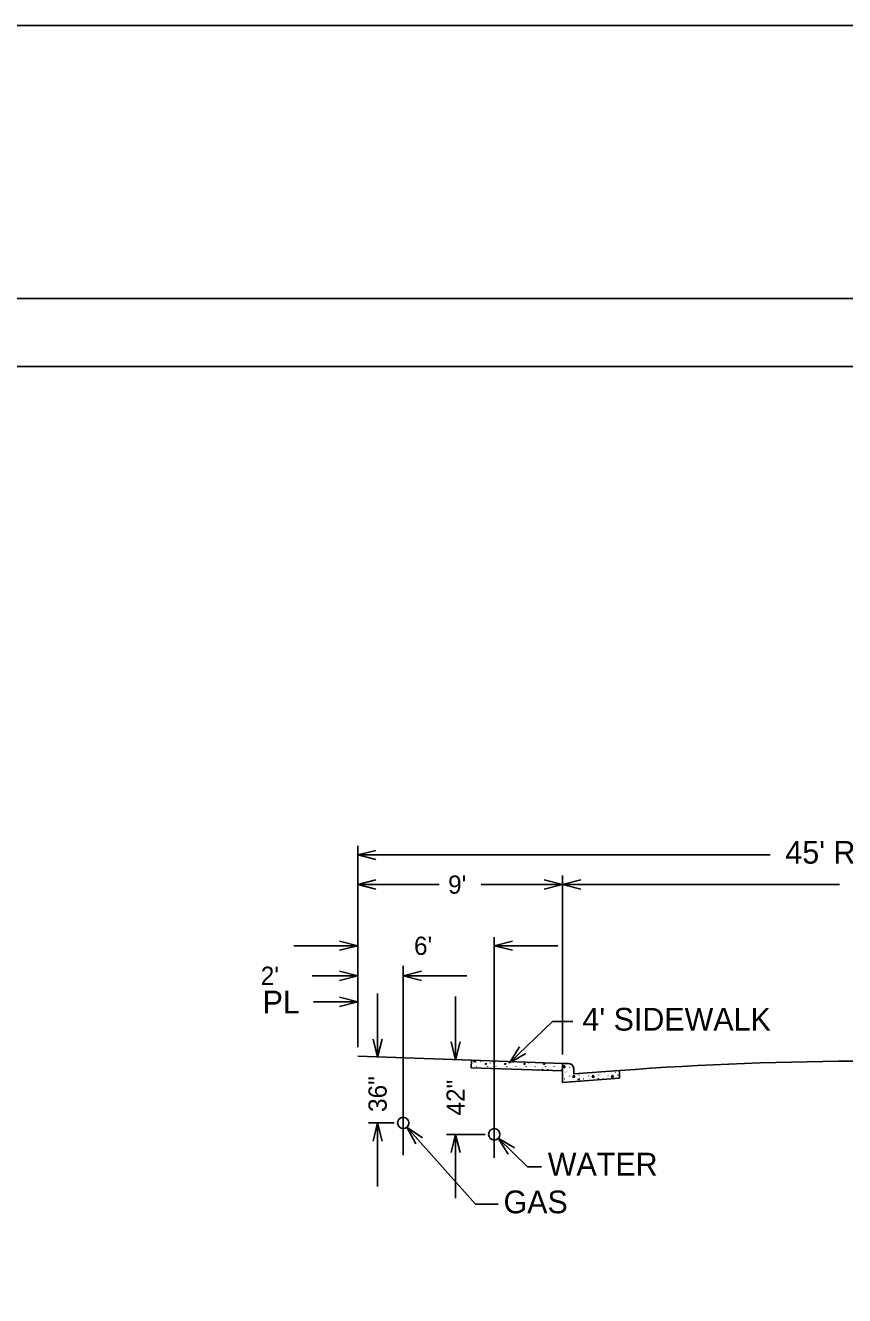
# Model space of a CAD drawing. Extents: x 524397 to 525117, y 3701341 to 3701821.
# Drawn here: x 524706.5 to 524778.5, y 3701709.3 to 3701821 of the extents above; entities that cross this region are included whole.
import ezdxf

# ---------------------------------------------------------------- set-up
doc = ezdxf.new("R2010")
doc.units = 0
for name, color, linetype in [('Level 1', 7, 'Continuous'), ('Level 11', 7, 'Continuous'), ('Level 9', 7, 'Continuous'), ('Pam batch print border', 7, 'Continuous')]:
    doc.layers.add(name, color=color, linetype=linetype)

msp = doc.modelspace()

# ---------------------------------------------------------------- linework, layer by layer
at = {"layer": 'Level 1'}
msp.add_line((524442.4, 3701790.98), (525097.4, 3701790.98), dxfattribs=at)
at = {"layer": 'Level 11'}
for p, q in [((524735.75, 3701731.14), (524735.75, 3701748.85)), ((524735.75, 3701748.05), (524737.35, 3701748.45)), ((524771.99, 3701748.05), (524735.75, 3701748.05)), ((524737.35, 3701747.65), (524735.75, 3701748.05)), ((524735.75, 3701731.28), (524735.75, 3701746.25)), ((524735.75, 3701745.45), (524737.35, 3701745.85)), ((524752.14, 3701745.85), (524753.75, 3701745.45)), ((524753.75, 3701730.51), (524753.75, 3701746.25)), ((524753.75, 3701745.45), (524755.35, 3701745.85)), ((524742.89, 3701745.45), (524735.75, 3701745.45)), ((524737.35, 3701745.05), (524735.75, 3701745.45)), ((524746.61, 3701745.45), (524753.75, 3701745.45)), ((524753.75, 3701745.45), (524752.14, 3701745.05)), ((524778.09, 3701745.45), (524753.75, 3701745.45)), ((524755.35, 3701745.05), (524753.75, 3701745.45)), ((524734.14, 3701740.46), (524735.75, 3701740.06)), ((524747.75, 3701721.41), (524747.75, 3701740.83)), ((524747.75, 3701740.06), (524749.35, 3701740.46)), ((524730.14, 3701740.06), (524735.75, 3701740.06)), ((524735.75, 3701740.06), (524734.14, 3701739.66)), ((524753.35, 3701740.06), (524747.75, 3701740.06)), ((524749.35, 3701739.66), (524747.75, 3701740.06)), ((524735.75, 3701731.51), (524735.75, 3701738.51)), ((524739.75, 3701721.64), (524739.75, 3701738.29)), ((524731.74, 3701737.42), (524735.75, 3701737.42)), ((524734.14, 3701737.82), (524735.75, 3701737.42)), ((524735.75, 3701737.42), (524734.14, 3701737.02)), ((524739.75, 3701737.42), (524741.35, 3701737.82)), ((524745.35, 3701737.42), (524739.75, 3701737.42)), ((524741.35, 3701737.02), (524739.75, 3701737.42)), ((524737.49, 3701735.87), (524737.49, 3701730.26)), ((524735.75, 3701735.13), (524731.87, 3701735.13)), ((524734.14, 3701735.53), (524735.75, 3701735.13)), ((524735.75, 3701735.13), (524734.14, 3701734.73)), ((524735.75, 3701731.51), (524735.75, 3701735.58)), ((524744.35, 3701735.6), (524744.35, 3701730)), ((524749.08, 3701729.78), (524752.86, 3701733.39)), ((524752.86, 3701733.39), (524754.66, 3701733.39)), ((524737.49, 3701730.26), (524737.09, 3701731.86)), ((524737.89, 3701731.86), (524737.49, 3701730.26)), ((524744.35, 3701730), (524743.95, 3701731.6)), ((524744.75, 3701731.6), (524744.35, 3701730)), ((524745.75, 3701729.99), (524735.75, 3701730.34)), ((524749.96, 3701731.18), (524749.08, 3701729.78)), ((524749.08, 3701729.78), (524750.51, 3701730.6)), ((524745.75, 3701729.99), (524745.73, 3701729.33)), ((524745.73, 3701729.33), (524753.75, 3701729.05)), ((524753.75, 3701729.71), (524745.75, 3701729.99)), ((524746.21, 3701729.45), (524746.2, 3701729.48)), ((524746.54, 3701729.86), (524746.52, 3701729.89)), ((524747.14, 3701729.44), (524747.12, 3701729.42)), ((524747.15, 3701729.45), (524747.14, 3701729.43)), ((524747.39, 3701729.77), (524747.39, 3701729.74)), ((524747.92, 3701729.45), (524747.9, 3701729.48)), ((524748.24, 3701729.86), (524748.23, 3701729.89)), ((524748.84, 3701729.44), (524748.83, 3701729.42)), ((524748.85, 3701729.45), (524748.84, 3701729.43)), ((524749.1, 3701729.77), (524749.09, 3701729.74)), ((524749.62, 3701729.45), (524749.6, 3701729.48)), ((524750.54, 3701729.44), (524750.53, 3701729.42)), ((524750.56, 3701729.45), (524750.54, 3701729.43)), ((524750.76, 3701729.18), (524750.75, 3701729.22)), ((524750.8, 3701729.77), (524750.79, 3701729.74)), ((524751.32, 3701729.45), (524751.3, 3701729.48)), ((524751.6, 3701729.13), (524751.59, 3701729.13)), ((524752.24, 3701729.44), (524752.23, 3701729.42)), ((524752.26, 3701729.45), (524752.24, 3701729.43)), ((524752.47, 3701729.18), (524752.45, 3701729.22)), ((524752.5, 3701729.76), (524752.5, 3701729.74)), ((524753.02, 3701729.45), (524753.01, 3701729.48)), ((524753.31, 3701729.1), (524753.29, 3701729.13)), ((524753.75, 3701728.05), (524753.75, 3701729.71)), ((524753.75, 3701729.71), (524754.26, 3701729.71)), ((524753.75, 3701729.05), (524753.75, 3701729.71)), ((524754.06, 3701728.94), (524754.05, 3701728.97)), ((524754.26, 3701729.71), (524754.25, 3701729.71)), ((524754.39, 3701729.35), (524754.37, 3701729.39)), ((524754.75, 3701729.25), (524754.75, 3701728.79)), ((524754.75, 3701728.79), (524758.75, 3701729.09)), ((524757.47, 3701728.94), (524757.45, 3701728.97)), ((524758.75, 3701729.09), (524758.75, 3701728.43)), ((524758.75, 3701728.43), (524753.75, 3701728.05)), ((524753.91, 3701728.37), (524753.89, 3701728.35)), ((524754.35, 3701728.6), (524754.34, 3701728.63)), ((524755.21, 3701728.68), (524755.2, 3701728.71)), ((524755.61, 3701728.37), (524755.6, 3701728.35)), ((524756.05, 3701728.6), (524756.04, 3701728.63)), ((524756.69, 3701728.93), (524756.68, 3701728.91)), ((524756.7, 3701728.94), (524756.69, 3701728.92)), ((524756.91, 3701728.68), (524756.9, 3701728.71)), ((524757.31, 3701728.37), (524757.3, 3701728.35)), ((524757.76, 3701728.6), (524757.74, 3701728.63)), ((524758.39, 3701728.93), (524758.38, 3701728.91)), ((524758.41, 3701728.94), (524758.39, 3701728.92)), ((524758.62, 3701728.68), (524758.6, 3701728.71)), ((524738.95, 3701724.48), (524736.69, 3701724.48)), ((524737.09, 3701722.88), (524737.49, 3701724.48)), ((524737.49, 3701718.88), (524737.49, 3701724.48)), ((524737.49, 3701724.48), (524737.89, 3701722.88)), ((524740.84, 3701722.64), (524740.07, 3701724.1)), ((524740.07, 3701724.1), (524741.44, 3701723.17)), ((524740.07, 3701724.1), (524746.1, 3701717.35)), ((524746.95, 3701723.48), (524743.55, 3701723.48)), ((524743.95, 3701721.88), (524744.35, 3701723.48)), ((524744.35, 3701717.88), (524744.35, 3701723.48)), ((524744.35, 3701723.48), (524744.75, 3701721.88)), ((524748.97, 3701721.73), (524748.1, 3701723.13)), ((524748.1, 3701723.13), (524749.53, 3701722.3)), ((524748.1, 3701723.13), (524750.67, 3701720.63)), ((524750.67, 3701720.63), (524751.91, 3701720.63)), ((524746.1, 3701717.35), (524748.09, 3701717.35))]:
    msp.add_line(p, q, dxfattribs=at)
for points in [[(524746.04, 3701729.98), (524745.95, 3701729.89), (524746.1, 3701729.82)], [(524746.11, 3701729.82), (524746.08, 3701729.98)], [(524747.07, 3701729.63), (524747.03, 3701729.72), (524746.96, 3701729.67), (524747.07, 3701729.63)], [(524747.68, 3701729.92), (524747.65, 3701729.89), (524747.8, 3701729.82)], [(524747.81, 3701729.82), (524747.79, 3701729.92)], [(524748.77, 3701729.63), (524748.73, 3701729.72), (524748.66, 3701729.67), (524748.77, 3701729.63)], [(524749.42, 3701729.86), (524749.51, 3701729.82)], [(524749.51, 3701729.82), (524749.5, 3701729.86)], [(524750.3, 3701729.17), (524750.29, 3701729.19), (524750.28, 3701729.17)], [(524750.47, 3701729.63), (524750.43, 3701729.72), (524750.36, 3701729.67), (524750.47, 3701729.63)], [(524752.03, 3701729.11), (524751.99, 3701729.19), (524751.96, 3701729.12)], [(524752.18, 3701729.63), (524752.13, 3701729.72), (524752.06, 3701729.67), (524752.18, 3701729.63)], [(524753.75, 3701729.09), (524753.69, 3701729.19), (524753.63, 3701729.06)], [(524753.96, 3701729.32), (524753.93, 3701729.52), (524753.8, 3701729.39), (524753.95, 3701729.32)], [(524754.42, 3701728.1), (524754.42, 3701728.11), (524754.4, 3701728.1)], [(524754.83, 3701728.5), (524754.74, 3701728.68), (524754.66, 3701728.52), (524754.83, 3701728.5)], [(524755.24, 3701728.28), (524755.19, 3701728.37), (524755.12, 3701728.31), (524755.24, 3701728.28)], [(524756.53, 3701728.5), (524756.44, 3701728.68), (524756.36, 3701728.52), (524756.53, 3701728.5)], [(524756.93, 3701728.29), (524756.9, 3701728.37), (524756.83, 3701728.31), (524756.9, 3701728.29)], [(524758.24, 3701728.5), (524758.14, 3701728.68), (524758.06, 3701728.52), (524758.23, 3701728.5)]]:
    msp.add_lwpolyline(points, dxfattribs=at)
for centre in [(524739.75, 3701724.48), (524747.75, 3701723.48)]:
    msp.add_circle(centre, 0.5, dxfattribs=at)
for centre, radius, start, end in [((524754.25, 3701729.22), 0.494, 3.7079, 90.7668), ((524780.75, 3701437.7), 292.22, 85.6824, 94.3176)]:
    msp.add_arc(centre, radius, start, end, dxfattribs=at)
at = {"layer": 'Level 9'}
msp.add_lwpolyline([(524396.79, 3701820.98), (525116.79, 3701820.98), (525116.79, 3701340.98), (524396.79, 3701340.98)], close=True, dxfattribs=at)
at = {"layer": 'Pam batch print border'}
msp.add_lwpolyline([(524433.4, 3701796.98), (525105.4, 3701796.98), (525105.4, 3701364.98), (524433.4, 3701364.98)], close=True, dxfattribs=at)
msp.add_lwpolyline([(524433.4, 3701796.98), (525105.4, 3701796.98), (525105.4, 3701364.98), (524433.4, 3701364.98)], close=True, dxfattribs=at)

# ---------------------------------------------------------------- texts
at = {"layer": 'Level 11'}
for s, height, p in [("45' R.O.W.", 2, (524773.34, 3701747.28)), ("9'", 1.601, (524743.69, 3701744.64)), ("6'", 1.601, (524740.69, 3701739.26)), ("2'", 1.601, (524727.22, 3701736.62)), ('PL', 2, (524727.38, 3701734.11)), ("4' SIDEWALK", 2, (524755.5, 3701732.6)), ('WATER', 2, (524752.45, 3701719.86)), ('GAS', 2, (524748.56, 3701716.54))]:
    msp.add_text(s, height=height, dxfattribs=at).set_placement(p)
for s, p in [('36"', (524738.29, 3701725.45)), ('42"', (524745.15, 3701725.14))]:
    msp.add_text(s, height=1.601, rotation=90, dxfattribs=at).set_placement(p)

doc.saveas('drawing.dxf')
